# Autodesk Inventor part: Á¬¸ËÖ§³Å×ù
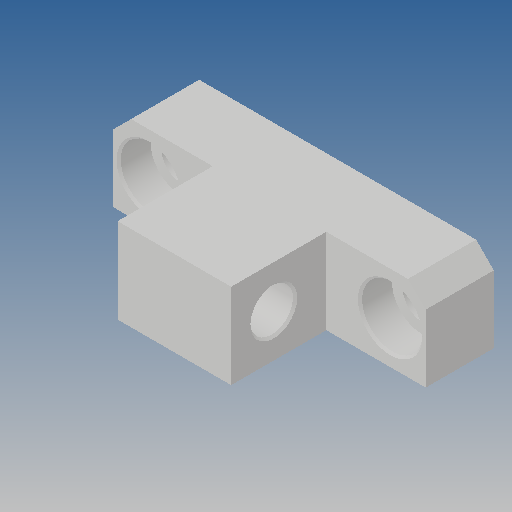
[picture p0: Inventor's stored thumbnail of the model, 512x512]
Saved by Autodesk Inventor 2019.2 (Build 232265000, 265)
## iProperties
Created: 2013-07
Part Number: Á¬¸ËÖ§³Å×ù
Material: Ogólny
Document SubType Name: Modeling
Designer: CADENGINEERING4
Density: 1 g/cm^3
Appearance: Domyślna
Author: CADENGINEERING4
Revision Number: ÈÎºÎ
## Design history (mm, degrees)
feature "µ¹½Ç3"
node "Bryła1"
